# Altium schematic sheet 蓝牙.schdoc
size 297 x 209 mm; Symbol: Drawing-Symbol_A4; @Create Time: 11:19:45; @Update Time: 16:56:06; Border: 1; Width: 1170; Height: 825; Region Start: 1; X Region Count: 6; Y Region Count: 4; Blade Width: 10; Title Block Position: 3; Title Block: 1; @Board Name: Board1; Company: 嘉立创EDA; Version: V1.0; Page Size: A4; @Project Name: stm32f4; @Page Count: 3; @Update Date: 2025-11-07; @Create Date: 2025-10-30; @Schematic Name: Schematic1; @Page No: 3; @Page Name: 蓝牙; Device: Drawing-Symbol_A4
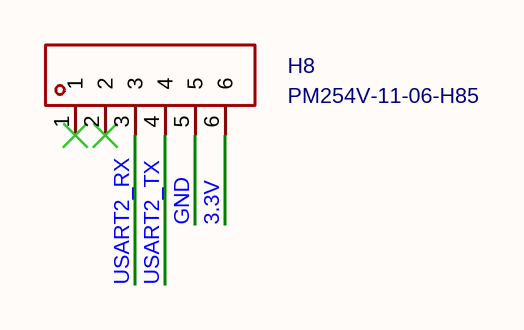
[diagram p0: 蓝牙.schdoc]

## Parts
H8  PM254V-11-06-H85  [HDR-TH_6P-P2.54-V-F]

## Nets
3.3V: H8.6
GND: H8.5
USART2_RX: H8.3
USART2_TX: H8.4

Not connected (* = marked no-connect by the designer): H8 1* 2*

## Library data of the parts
H8 = PM254V-11-06-H85: 插孔结构:1x6P;间距:2.54mm;行距:-;圆孔/方孔:方孔;安装方式:直插;排数:单排;总孔位数:6P;额定电流:3A;额定电压:250V;插孔方向:顶部;塑高:-;工作温度:-40℃~+105℃;; Manufacturer: XFCN(兴飞); AddInBom: yes; ModelId: 0f5bcf94dcda47d085f24cdca1696fe9; ModelTransform: 619.684,94.488,0,0,0,0,0,0,-125.984; Holes Structure: 1x6P; Pitch: 2.54mm; Circular Hole / Square Hole: 方孔; Number of Positions: 6P; Current Rating: 3A; Voltage Rating (Max): 250V; Holes Direction: 顶部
